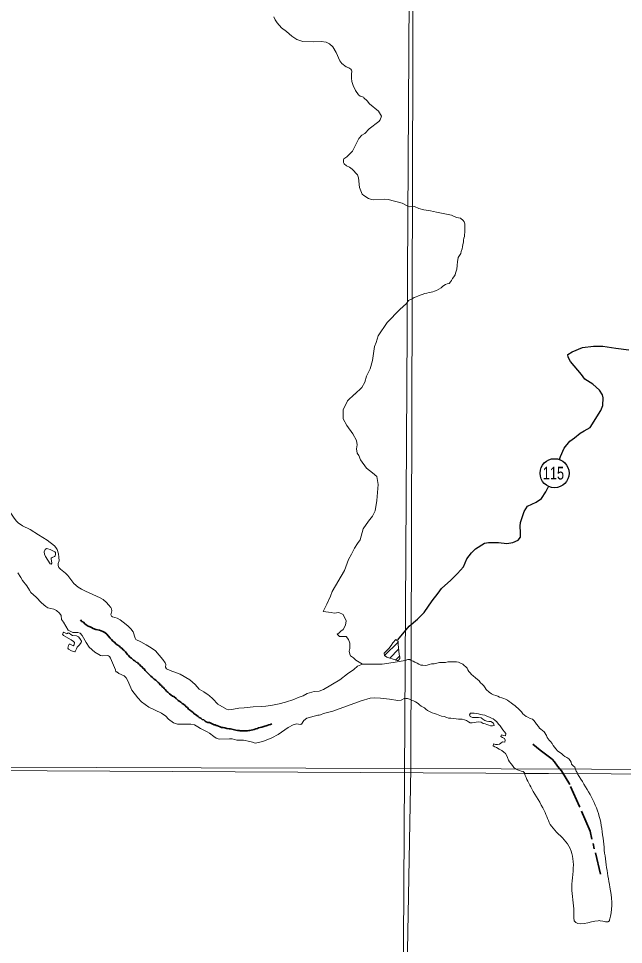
# Model space of a CAD drawing. Extents: x 553962 to 842807, y 8883888 to 9032388.
# Drawn here: x 605379 to 608716, y 8897864 to 8902976 of the extents above; entities that cross this region are included whole.
import ezdxf
from ezdxf.enums import TextEntityAlignment as Align

# ---------------------------------------------------------------- set-up
doc = ezdxf.new("R2010")
doc.units = 0
doc.header["$LTSCALE"] = 20
doc.linetypes.add('LONG_DASH_SHORT_DASH', pattern=[9.9, 6, -1.2, 1.5, -1.2])
doc.layers.add('6', color=7, linetype='Continuous', lineweight=13)

msp = doc.modelspace()

# ---------------------------------------------------------------- linework, layer by layer
at = {"layer": '6'}
for p, q in [((607398.17, 8899458.87), (607473.31, 8899534.01)), ((607427.1, 8899445.38), (607475.97, 8899494.24)), ((607458.9, 8899434.74), (607481.08, 8899456.93)), ((608462.44, 8898805.76), (608169.36, 8898807.76))]:
    msp.add_line(p, q, dxfattribs=at)
for points in [[(607657.67, 8924743.35), (607574.22, 8909874.89), (607492.34, 8896026.67)], [(606788.04, 8902984.87), (606794.73, 8902968.14), (606805.97, 8902952.71), (606830.18, 8902925.42), (606857.14, 8902905.05), (606886.26, 8902878.8), (606914.43, 8902860.1), (606948.01, 8902848.93), (607006.56, 8902848.11), (607048.08, 8902849.71), (607075.35, 8902846.42), (607093.9, 8902836.45), (607113.61, 8902820.63), (607131.93, 8902788.25), (607150.86, 8902742.38), (607162.03, 8902727.53), (607185.97, 8902709.19), (607201.27, 8902703.37), (607212.58, 8902696.13), (607216.16, 8902691.53), (607217.84, 8902685.39), (607215.38, 8902668.19), (607214.93, 8902646.17), (607217.08, 8902629.11), (607225.16, 8902606.77), (607238.21, 8902578.87), (607253.82, 8902555.23), (607264.33, 8902547.47), (607282.67, 8902541.66), (607283.57, 8902539.04), (607302.01, 8902521), (607314.65, 8902506.06), (607364.06, 8902464.6), (607381.07, 8902436.97), (607373.8, 8902416.86), (607366.91, 8902407.51), (607313.23, 8902367.6), (607289.86, 8902342.28), (607273.64, 8902332.11), (607256.09, 8902313.64), (607221.85, 8902244.36), (607189.32, 8902212.45), (607173.86, 8902201.25), (607171.63, 8902197.44), (607171.21, 8902181.63), (607174.74, 8902173.24), (607187.79, 8902163.1), (607205.47, 8902154.97), (607219.12, 8902145.24), (607248.38, 8902113.68), (607254.27, 8902096.16), (607259.31, 8902043.78), (607274.55, 8902006.99), (607283.93, 8901998.8), (607310.06, 8901983.35), (607326.64, 8901977.45), (607338.07, 8901975.51), (607395.08, 8901979.08), (607418.6, 8901977.93), (607495.8, 8901956.34), (607527.17, 8901939.73)], [(607527.17, 8901939.73), (607536.15, 8901936.97), (607536.15, 8901936.97), (607562.78, 8901938.08), (607562.78, 8901938.08), (607562.78, 8901938.08), (607587.2, 8901928.1)], [(607587.2, 8901928.1), (607614.94, 8901919.22), (607614.94, 8901919.22), (607614.94, 8901919.22), (607614.94, 8901919.22), (607651.56, 8901913.68), (607651.56, 8901913.68), (607651.56, 8901913.68), (607684.86, 8901908.13), (607684.86, 8901908.13), (607684.86, 8901908.13), (607740.34, 8901895.93), (607740.34, 8901895.93), (607740.34, 8901895.93), (607740.34, 8901895.93), (607768.09, 8901890.39), (607768.09, 8901890.39), (607768.09, 8901890.39), (607794.72, 8901878.19), (607818.03, 8901873.75), (607831.66, 8901862.02), (607837.71, 8901853.84), (607841.71, 8901843.62), (607841.64, 8901833.43), (607841.55, 8901821.21), (607840.45, 8901807.97), (607840.36, 8901794.73), (607839.27, 8901784.55), (607839.19, 8901773.34), (607835.06, 8901764.2), (607833.96, 8901753), (607832.86, 8901740.78), (607830.75, 8901728.57), (607827.6, 8901715.35), (607825.5, 8901705.17), (607821.32, 8901689.92), (607818.2, 8901679.75), (607812.02, 8901668.58), (607804.82, 8901656.4), (607801.68, 8901644.2), (607800.6, 8901634.02), (607797.9, 8901612.03)], [(607797.9, 8901612.03), (607796.24, 8901592.28), (607794.13, 8901582.1), (607789.99, 8901570.92), (607786.87, 8901560.76), (607780.69, 8901549.59), (607773.5, 8901540.47), (607768.35, 8901530.31), (607761.17, 8901522.21), (607753.99, 8901514.1), (607743.8, 8901511.11), (607734.62, 8901507.1), (607724.42, 8901503.09), (607717.25, 8901496), (607710.08, 8901488.92), (607697.83, 8901481.86), (607685.57, 8901474.81), (607674.36, 8901471.83), (607665.18, 8901467.81), (607654.98, 8901464.82), (607643.79, 8901463.87), (607630.54, 8901460.9), (607620.36, 8901458.93), (607606.07, 8901452.91), (607594.86, 8901449.92), (607582.62, 8901443.89), (607572.42, 8901439.88), (607561.21, 8901436.89), (607550.98, 8901428.81), (607530.56, 8901418.75), (607518.61, 8901403.86)], [(607518.61, 8901403.86), (607482.06, 8901370.65), (607412.27, 8901297.59), (607362.43, 8901224.52), (607352.46, 8901187.99), (607342.49, 8901164.74), (607332.52, 8901088.36), (607319.22, 8901041.86), (607299.29, 8901002.01), (607289.32, 8900968.8), (607272.71, 8900938.91), (607233.87, 8900903.33)], [(607232.83, 8900902.38), (607192.95, 8900865.85), (607169.7, 8900816.03), (607169.7, 8900766.21), (607189.64, 8900729.69), (607222.86, 8900683.19), (607242.81, 8900646.66), (607246.12, 8900623.41), (607242.81, 8900600.16), (607246.12, 8900576.91), (607256.1, 8900563.63), (607266.07, 8900540.38), (607299.29, 8900493.89), (607332.53, 8900467.32), (607355.79, 8900447.4), (607362.43, 8900404.22), (607355.79, 8900314.55), (607345.81, 8900258.09), (607332.53, 8900228.2), (607309.26, 8900201.64), (607279.36, 8900158.46), (607262.74, 8900098.68), (607249.45, 8900078.76), (607232.83, 8900052.19), (607216.22, 8900018.97), (607199.61, 8899989.08), (607176.35, 8899929.31), (607109.89, 8899813.07), (607099.92, 8899786.5), (607079.98, 8899743.32), (607060.04, 8899703.47), (607103.24, 8899696.83), (607119.85, 8899693.51), (607146.44, 8899696.83), (607169.7, 8899686.86), (607186.31, 8899650.33), (607182.99, 8899627.08), (607169.7, 8899603.84), (607156.4, 8899593.88), (607146.44, 8899583.91), (607136.47, 8899577.27), (607149.76, 8899563.98), (607186.31, 8899563.98), (607199.61, 8899547.38), (607206.25, 8899527.45), (607206.25, 8899507.53), (607206.25, 8899497.57), (607202.93, 8899484.28), (607206.25, 8899467.67), (607209.57, 8899457.71), (607226.19, 8899447.75), (607239.48, 8899434.46), (607276.03, 8899411.22)], [(605318.42, 8900257.25), (605328.14, 8900253.16), (605335.8, 8900246.19), (605350.87, 8900222.77), (605366.06, 8900202.71), (605377.32, 8900192.35), (605399.92, 8900175.56), (605442.27, 8900156.22), (605489.34, 8900126.6)], [(605489.34, 8900126.6), (605536.4, 8900096.97), (605576.27, 8900065.92), (605584.03, 8900055.76)], [(605584.03, 8900055.76), (605591.8, 8900045.61), (605599.46, 8900021.77), (605601.28, 8900001.94)], [(605601.28, 8900001.94), (605603.1, 8899982.11), (605597.89, 8899967.46), (605596.61, 8899956.96), (605600.19, 8899946.07), (605609.64, 8899935.65), (605637.01, 8899914.37), (605637.01, 8899914.37), (605649.84, 8899902), (605684.47, 8899857.47), (605707.87, 8899837.1), (605725.15, 8899825.07), (605748.78, 8899814.47)], [(605438.85, 8899820.49), (605424.47, 8899844.69), (605400.28, 8899874.52), (605391.87, 8899891.13), (605374.33, 8899916.5)], [(605651.92, 8899599.22), (605627.2, 8899644.19), (605614.88, 8899659.32), (605613, 8899679.97), (605604.77, 8899694.21), (605588.81, 8899707.75), (605573.84, 8899716.35), (605540.9, 8899723.14), (605528.66, 8899729.82), (605504.88, 8899751.32), (605476.06, 8899781.55), (605446.9, 8899806.95), (605438.85, 8899820.49)], [(605748.78, 8899814.47), (605828.89, 8899778.55), (605845.58, 8899768.38), (605864.64, 8899753.22), (605875.88, 8899739.1)], [(605875.88, 8899739.1), (605887.13, 8899724.97), (605890.75, 8899718.06), (605893.55, 8899706.3), (605887.94, 8899684.92), (605892.46, 8899676.46), (605897.05, 8899672.9), (605922.32, 8899665.23), (605940.15, 8899656.12), (605972.74, 8899630.67), (605982.63, 8899621.66)], [(605800.36, 8899478.27), (605768.67, 8899506.15), (605752.14, 8899530.81), (605730.47, 8899570.06), (605719.18, 8899583.89), (605705.97, 8899587.44), (605690.94, 8899586.33), (605677.79, 8899587.4), (605651.92, 8899599.22)], [(605982.63, 8899621.66), (605997.93, 8899607.72), (606011.09, 8899590.17), (606021.77, 8899555.14), (606026.3, 8899548.71), (606053.9, 8899535.25), (606082.64, 8899518.19)], [(606082.64, 8899518.19), (606110.4, 8899501.72), (606133.75, 8899485.14), (606175.03, 8899438.13), (606188.25, 8899420.07), (606191.48, 8899410.33), (606189.48, 8899394.84), (606194.93, 8899386.65), (606215.55, 8899376.75), (606270.88, 8899356.22), (606324.13, 8899326.32), (606338.99, 8899313.29)], [(605886.78, 8899444.23), (605880.49, 8899454.05), (605875.63, 8899458.01), (605871.79, 8899459.03), (605843.64, 8899457.85), (605831.77, 8899459.59), (605821.4, 8899464.59), (605800.36, 8899478.27)], [(606167.03, 8899141.33), (606097.76, 8899173.83), (606057.38, 8899203.21), (606036.35, 8899225.66), (606003.39, 8899268.52), (605981.95, 8899319.32), (605972.66, 8899335.84), (605960.87, 8899348.22), (605932.75, 8899360.82), (605920.3, 8899368.72), (605915.99, 8899369.44), (605914.16, 8899381.16), (605886.78, 8899444.23)], [(606996.27, 8899256.74), (607009.09, 8899260.47), (607037.25, 8899263.04), (607061.25, 8899271.73), (607150.54, 8899324.71), (607193.66, 8899358.82), (607228.54, 8899383.03), (607248.69, 8899401.58), (607276.03, 8899411.22), (607305.94, 8899411.22), (607385.69, 8899411.22), (607445.51, 8899421.18), (607512.32, 8899432.53)], [(607512.32, 8899432.53), (607525.91, 8899438.29), (607537.1, 8899438.22), (607545.19, 8899432.05), (607555.34, 8899427.91), (607565.47, 8899422.76), (607577.64, 8899416.56), (607586.76, 8899411.41), (607597.92, 8899407.27), (607609.1, 8899406.18), (607621.3, 8899405.08), (607633.51, 8899406.02), (607643.71, 8899410.03), (607657.98, 8899412.99), (607671.21, 8899413.93), (607701.77, 8899420.86), (607712.96, 8899420.79), (607723.13, 8899420.73), (607734.32, 8899420.65), (607747.57, 8899424.64), (607757.74, 8899424.58), (607769.95, 8899424.5), (607783.17, 8899424.42), (607795.38, 8899424.34), (607806.56, 8899422.23), (607817.72, 8899418.08), (607830.9, 8899411.88), (607837.97, 8899404.71), (607846.06, 8899397.52), (607853.13, 8899390.35)], [(607853.13, 8899390.35), (607858.15, 8899381.15), (607863.17, 8899371.95), (607871.26, 8899363.74), (607878.32, 8899355.55), (607887.42, 8899347.34), (607899.55, 8899336.05), (607919.78, 8899319.62), (607927.85, 8899309.39), (607936.95, 8899302.2), (607946.04, 8899292.97), (607954.1, 8899280.69), (607959.12, 8899271.49), (607975.31, 8899258.14), (607987.44, 8899247.88), (607998.6, 8899242.71), (608011.79, 8899238.55), (608022.96, 8899235.42), (608033.1, 8899230.26), (608045.27, 8899226.11), (608056.44, 8899221.96), (608065.56, 8899217.83), (608075.7, 8899212.67), (608085.82, 8899205.48), (608096.97, 8899199.29), (608108.1, 8899190.05), (608116.18, 8899182.87), (608124.28, 8899176.7), (608135.4, 8899166.44), (608142.47, 8899159.27), (608154.6, 8899147.98), (608160.63, 8899137.76), (608178.84, 8899123.38), (608188.99, 8899119.24), (608202.16, 8899112.02), (608214.35, 8899108.89), (608222.44, 8899101.7), (608228.48, 8899092.5), (608236.54, 8899081.24), (608246.62, 8899067.93), (608252.66, 8899058.72), (608260.75, 8899052.56), (608269.86, 8899046.39), (608278.96, 8899038.18), (608291.04, 8899018.74), (608295.03, 8899007.51), (608306.11, 8898992.16), (608314.2, 8898984.98), (608322.26, 8898973.72), (608329.31, 8898963.48), (608335.34, 8898953.26), (608342.41, 8898945.06), (608352.5, 8898933.79), (608365.66, 8898923.52), (608374.78, 8898918.37), (608383.88, 8898910.16), (608392.98, 8898902.97), (608403.1, 8898895.77), (608414.25, 8898889.59), (608421.31, 8898880.37), (608427.34, 8898870.15), (608430.32, 8898859.94), (608439.42, 8898850.71), (608447.5, 8898843.53), (608451.5, 8898832.3)], [(606338.99, 8899313.29), (606353.84, 8899300.25), (606375.85, 8899273.58), (606401.27, 8899259.48), (606425.55, 8899243.47), (606430.28, 8899239.22)], [(606430.28, 8899239.22), (606451.11, 8899220.49), (606477.91, 8899191.59), (606526.1, 8899162.91), (606538.79, 8899160.41), (606552.27, 8899160.95), (606564.82, 8899163.38)], [(606850.86, 8899202.66), (606897.35, 8899217.33), (606921.29, 8899228.17), (606948.87, 8899237.73), (606970.76, 8899249.32), (606996.27, 8899256.74)], [(606743.45, 8899180.84), (606780.19, 8899185.1), (606817.39, 8899192.09), (606850.86, 8899202.66)], [(607510.32, 8899223.38), (607489.46, 8899213.79), (607472.27, 8899210.62), (607425.68, 8899218.6), (607376, 8899224.92), (607343.23, 8899226.88), (607318.71, 8899223.81), (607269.57, 8899209.61), (607112.03, 8899153.13), (607061.57, 8899139.37), (607044.89, 8899132.08), (607038.25, 8899131.22)], [(607965.23, 8899123.73), (607951.03, 8899129.93), (607937.82, 8899133.07), (607926.64, 8899133.15), (607916.49, 8899137.29), (607906.34, 8899140.41), (607892.1, 8899140.5), (607872.77, 8899140.62), (607866.61, 8899132.51), (607870.61, 8899122.3), (607882.78, 8899117.13), (607893.97, 8899117.05), (607904.15, 8899116.99), (607917.37, 8899116.9), (607930.59, 8899115.8), (607940.7, 8899107.59), (607950.83, 8899101.41), (607963.01, 8899097.26), (607974.19, 8899096.16), (607984.36, 8899096.1), (607999.55, 8899085.81), (608003.54, 8899073.56), (607993.34, 8899070.57), (607983.17, 8899070.64), (607973.03, 8899074.78), (607961.87, 8899078.92), (607952.74, 8899083.06), (607941.56, 8899084.15), (607930.42, 8899092.37), (607917.21, 8899093.47), (607902.96, 8899092.55), (607892.77, 8899089.56), (607881.57, 8899088.61), (607870.38, 8899088.68), (607861.26, 8899093.83), (607850.12, 8899100.02), (607839.97, 8899104.16), (607826.78, 8899108.32), (607816.6, 8899108.38), (607806.43, 8899108.45), (607793.22, 8899109.55), (607777.98, 8899112.7), (607763.74, 8899113.81), (607751.54, 8899113.89), (607741.39, 8899118.03), (607727.18, 8899122.2), (607711.95, 8899125.35), (607693.68, 8899131.58), (607684.56, 8899136.74), (607674.41, 8899139.86), (607661.21, 8899144.02), (607646, 8899150.23), (607634.84, 8899155.39), (607625.74, 8899163.6), (607617.65, 8899170.78), (607600.43, 8899180.06), (607591.33, 8899188.27), (607583.23, 8899194.44), (607569.05, 8899203.7), (607557.9, 8899208.86), (607547.75, 8899211.98), (607536.6, 8899218.17), (607525.44, 8899222.31), (607515.27, 8899222.38), (607510.32, 8899223.38)], [(606368.43, 8899065.69), (606348.91, 8899077.01), (606328.98, 8899080.19), (606255.6, 8899080.86), (606233.84, 8899088.85), (606206.95, 8899108.77), (606191.59, 8899125.09), (606167.03, 8899141.33)], [(606564.82, 8899163.38), (606594.83, 8899169.21), (606623.97, 8899170.23), (606672.95, 8899176.27), (606719.72, 8899178.1), (606743.45, 8899180.84)], [(607038.25, 8899131.22), (607030.14, 8899130.18), (606968.5, 8899113.87), (606953.54, 8899101.63), (606940.78, 8899080.46), (606936.88, 8899079.85)], [(608076.57, 8898895.83), (608072.57, 8898905.02), (608064.52, 8898918.32), (608056.43, 8898925.5), (608045.31, 8898934.74), (608031.12, 8898942.98), (608015.93, 8898952.25), (608006.8, 8898956.38), (607996.66, 8898961.54), (607999.78, 8898971.71), (608010.95, 8898968.58), (608022.14, 8898968.51), (608032.32, 8898969.46), (608040.51, 8898976.54), (608048.69, 8898982.6), (608060.89, 8898981.51), (608064.01, 8898992.69), (608058.99, 8899001.89), (608048.85, 8899007.05), (608039.74, 8899013.22), (608043.87, 8899022.37), (608054.01, 8899017.21), (608066.22, 8899017.13), (608067.32, 8899029.35), (608059.24, 8899038.57), (608051.18, 8899049.83), (608044.14, 8899061.08), (608036.08, 8899072.34), (608026.98, 8899080.54), (608017.91, 8899092.83), (608005.77, 8899102.07), (607997.68, 8899110.28), (607987.53, 8899113.4), (607977.4, 8899119.58), (607965.23, 8899123.73)], [(606669.71, 8898980.46), (606654.61, 8898985.76), (606620, 8898992.46), (606583.12, 8898992.22), (606556.53, 8898999.11), (606542.71, 8899000.38), (606485.27, 8898997.17), (606468.8, 8899003.82), (606455.29, 8899011.79), (606431.99, 8899031.1), (606419.71, 8899039.23), (606382.69, 8899057.42), (606368.43, 8899065.69)], [(606936.88, 8899079.85), (606931.93, 8899079.08), (606913.39, 8899083.39), (606894.36, 8899077.05), (606866.55, 8899063.01), (606810.71, 8899023.73), (606775.99, 8899005.78), (606726.3, 8898985.27), (606684.82, 8898975.17), (606669.71, 8898980.46)], [(574695.3, 8898953.23), (596544.27, 8898870.44), (626625.69, 8898710.85)], [(608169.36, 8898807.76), (608170.6, 8898811.69), (608162.51, 8898818.87), (608151.33, 8898820.98), (608142.21, 8898825.11), (608132.06, 8898829.25), (608120.9, 8898833.4), (608110.79, 8898841.61), (608104.76, 8898852.86), (608096.68, 8898862.08), (608087.61, 8898873.35), (608081.57, 8898882.55), (608076.57, 8898895.83)], [(608451.5, 8898832.3), (608454.48, 8898822.09), (608460.52, 8898813.9), (608462.44, 8898805.76), (608169.36, 8898807.76)]]:
    msp.add_lwpolyline(points, dxfattribs=at)
for points in [[(618535.25, 8909853.32), (607574.31, 8909890.72), (607543.3, 8898835.28), (618504.23, 8898795.81)], [(605577.96, 8900006.42), (605581.13, 8900009.73), (605583.1, 8900017.17), (605581.82, 8900027.92), (605579.61, 8900031.92), (605553.78, 8900045.19), (605540.63, 8900049.44), (605532.21, 8900049.61), (605526.49, 8900045.69), (605520.86, 8900031.33), (605522.28, 8900018.29), (605527.3, 8900006.56), (605552.8, 8899966.1), (605559.02, 8899963.93), (605562.65, 8899968.71), (605558.58, 8899992.7), (605559.4, 8899996.77), (605563.91, 8900000.57)], [(605726.49, 8899537.94), (605724.01, 8899530.64), (605714.43, 8899518.16), (605702.97, 8899506.07), (605697.81, 8899496.64), (605691.76, 8899481.47), (605690.04, 8899479.84), (605670.67, 8899486.14), (605654.23, 8899494.29), (605651.4, 8899501.09), (605654.21, 8899514.3), (605658.72, 8899522.46), (605659.81, 8899522.99), (605664.42, 8899521.95), (605679.95, 8899513.5), (605686.36, 8899517.98), (605687.1, 8899532.41), (605682.55, 8899537.52), (605669.01, 8899546.23), (605627.12, 8899569.73), (605621.02, 8899577.27), (605624.06, 8899584.77), (605629.49, 8899588.48), (605644.86, 8899579.37), (605648.74, 8899580.64), (605650.35, 8899583.7), (605653.31, 8899585.59), (605658.05, 8899583.37), (605667.74, 8899575.21), (605676.28, 8899570.59), (605698.75, 8899568.75), (605709.73, 8899562.82), (605717.54, 8899553.15), (605726.29, 8899538.89)], [(607460.51, 8899548.43), (607473.37, 8899537.39), (607473.07, 8899520.74), (607478.95, 8899466.95), (607482.51, 8899450.23), (607481.52, 8899443.67), (607477.77, 8899435.07), (607475, 8899432.45), (607467.53, 8899432.48), (607456.82, 8899435.29), (607411.12, 8899450.8), (607397.82, 8899459.08), (607396.21, 8899472.69), (607398.89, 8899476.48), (607421.74, 8899498.11), (607434.38, 8899514.64), (607443.22, 8899529.04)], [(596544.27, 8898870.44), (596531.66, 8896026.67), (607492.34, 8896026.67), (607543.3, 8898835.28)]]:
    msp.add_lwpolyline(points, close=True, dxfattribs=at)
at = {"layer": '6', "lineweight": 25}
for points in [[(608362.46, 8900541.86), (608368.22, 8900558.39), (608389.79, 8900605.22), (608420.49, 8900642.86), (608446.03, 8900662.17), (608477.71, 8900686.56), (608500.17, 8900699.76), (608531.83, 8900719.06), (608592.28, 8900811.66), (608601.56, 8900840.17), (608604.77, 8900882.96), (608599.74, 8900899.27), (608584.55, 8900924.77), (608547.99, 8900957.44), (608502.24, 8900986.05), (608484, 8901011.55), (608424.15, 8901082.98), (608410.99, 8901106.44), (608410.02, 8901120.7), (608433.52, 8901136.96), (608490.66, 8901160.29), (608550.8, 8901168.33), (608602.76, 8901168.23), (608674.04, 8901155.87), (608745.33, 8901147.59)], [(607472.23, 8899545.85), (607534.39, 8899621.59), (607579.37, 8899661.24), (607616.18, 8899696.83), (607661.25, 8899761.95), (607694.01, 8899804.68), (607711.42, 8899829.1), (607763.56, 8899875.87), (607801.39, 8899912.48), (607833.11, 8899950.12), (607852.63, 8899993.89), (607877.2, 8900026.45), (607900.72, 8900048.82), (607948.72, 8900079.3), (607972.17, 8900084.35), (608027.19, 8900083.23), (608072, 8900078.05), (608106.66, 8900084.1), (608135.23, 8900096.27), (608147.52, 8900113.57), (608148.64, 8900139.04), (608146.73, 8900173.68), (608147.82, 8900194.06), (608168.42, 8900255.15), (608186.87, 8900283.64), (608234.84, 8900305.97), (608263.44, 8900327.31), (608288.03, 8900363.94), (608301.37, 8900388.37), (608303.74, 8900393.09)]]:
    msp.add_lwpolyline(points, dxfattribs=at)
at = {"layer": '6', "linetype": 'LONG_DASH_SHORT_DASH', "lineweight": 35}
for points in [[(605956.76, 8899491.27), (605948.62, 8899499.45), (605941.49, 8899504.05), (605935.89, 8899511.21), (605923.67, 8899519.39), (605916.04, 8899523.99), (605907.89, 8899532.68), (605899.75, 8899538.31), (605891.6, 8899548.53), (605884.48, 8899554.67), (605873.28, 8899567.45), (605865.13, 8899577.67), (605854.95, 8899586.87), (605844.26, 8899591.98), (605825.43, 8899599.65), (605805.58, 8899603.23), (605791.33, 8899609.37), (605781.66, 8899613.46), (605773.01, 8899617.54), (605763.33, 8899621.63), (605758.24, 8899625.72), (605751.63, 8899628.79), (605744.5, 8899635.44), (605736.86, 8899643.11), (605728.72, 8899648.22), (605721.15, 8899657.33)], [(606202.14, 8899256.62), (606197.05, 8899261.73), (606188.39, 8899272.47), (606181.77, 8899277.07), (606178.21, 8899283.72), (606171.08, 8899287.3), (606167.01, 8899293.94), (606159.37, 8899298.03), (606155.3, 8899306.21), (606148.17, 8899311.32), (606136.97, 8899323.59), (606127.3, 8899328.19), (606117.12, 8899337.91), (606107.96, 8899345.58), (606097.27, 8899355.8), (606091.16, 8899361.42), (606084.03, 8899370.11), (606076.9, 8899377.78), (606072.32, 8899385.45), (606065.2, 8899389.54), (606061.12, 8899397.21), (606054, 8899400.79), (606046.87, 8899410.5), (606039.74, 8899414.08), (606035.16, 8899420.21), (606028.03, 8899423.79), (606020.91, 8899430.44), (606013.78, 8899434.02), (606005.63, 8899440.66), (606001.05, 8899444.75), (605993.42, 8899450.89), (605985.78, 8899460.09), (605980.69, 8899465.71), (605973.05, 8899474.91), (605968.47, 8899480.03), (605961.34, 8899486.67), (605956.76, 8899491.27)], [(606696.35, 8899056.23), (606688.71, 8899055.72), (606679.05, 8899051.63), (606671.41, 8899049.07), (606662.76, 8899047.54), (606654.62, 8899046), (606649.02, 8899044.98), (606641.9, 8899043.96), (606630.19, 8899043.96), (606622.56, 8899043.96), (606614.42, 8899043.96), (606609.84, 8899043.96), (606602.21, 8899044.47), (606596.61, 8899044.98), (606586.94, 8899046.51), (606578.29, 8899048.05), (606570.14, 8899049.58), (606562.51, 8899051.11), (606554.88, 8899052.65), (606548.26, 8899054.18), (606540.12, 8899055.71), (606528.41, 8899057.25), (606517.72, 8899060.32), (606508.05, 8899061.85), (606498.89, 8899061.85), (606490.75, 8899065.94), (606481.08, 8899069.52), (606472.94, 8899072.58), (606468.87, 8899073.61), (606462.76, 8899076.67), (606458.69, 8899077.7), (606451.05, 8899081.27), (606446.47, 8899082.3), (606439.85, 8899086.39), (606432.22, 8899089.97), (606423.57, 8899090.48), (606414.41, 8899094.05), (606408.3, 8899097.63), (606400.66, 8899103.77), (606392.52, 8899106.84), (606384.37, 8899113.48), (606375.72, 8899116.55), (606370.12, 8899122.68), (606362.49, 8899127.8), (606355.36, 8899133.93), (606347.72, 8899138.02), (606342.63, 8899144.67), (606336.02, 8899148.75), (606326.85, 8899156.93), (606316.67, 8899162.56), (606311.58, 8899171.76), (606303.95, 8899176.36), (606297.33, 8899183.52), (606288.16, 8899190.68), (606281.55, 8899194.76), (606273.4, 8899202.43), (606268.31, 8899205.5), (606260.17, 8899212.15), (606255.59, 8899215.21), (606247.95, 8899222.88), (606236.24, 8899232.6), (606227.59, 8899235.15), (606219.44, 8899243.33), (606211.3, 8899247.42), (606202.14, 8899256.62)], [(606776.91, 8899082.34), (606776.74, 8899082.3), (606768.6, 8899079.24), (606759.44, 8899076.17), (606750.79, 8899073.61), (606731.46, 8899067.48), (606720.77, 8899063.9), (606711.61, 8899061.34), (606701.94, 8899060.32), (606696.35, 8899056.23)], [(608589.68, 8898253.18), (608531.8, 8898489.64), (608473.81, 8898626.9), (608419.68, 8898746.76), (608375.21, 8898822.16), (608352.01, 8898849.22), (608336.54, 8898872.3), (608323.35, 8898886.59), (608292.87, 8898910.08), (608256.29, 8898937.65), (608216.65, 8898970.6)]]:
    msp.add_lwpolyline(points, dxfattribs=at)
at = {"layer": '6', "lineweight": 25}
msp.add_circle((608336.26, 8900466.07), 80.26, dxfattribs=at)
at = {"layer": '6'}
msp.add_spline([(608169.36, 8898807.76), (608210.01, 8898723.56), (608278.78, 8898603.22), (608318.89, 8898517.27), (608399.11, 8898431.31), (608439.23, 8898322.44), (608430.63, 8898179.18), (608442.09, 8898044.51), (608442.06, 8898015.41), (608444.96, 8897995.81), (608576.75, 8897995.81), (608588.21, 8897995.81), (608638.52, 8897995.77), (608640.52, 8898005.2), (608644.24, 8898020.07), (608641.49, 8898180.13), (608620.76, 8898304.51), (608605.41, 8898434.18), (608582.48, 8898571.71), (608462.44, 8898805.76)], degree=3, dxfattribs=at)

# ---------------------------------------------------------------- texts
at = {"layer": '6', "width": 0.75}
msp.add_text('115', height=70, dxfattribs=at).set_placement((608329.94, 8900431.41), align=Align.CENTER)

doc.saveas('drawing.dxf')
